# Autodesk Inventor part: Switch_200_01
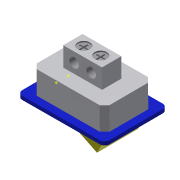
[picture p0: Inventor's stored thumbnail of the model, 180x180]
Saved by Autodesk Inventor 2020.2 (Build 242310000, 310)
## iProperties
Created: 2014-09
Part Number: Switch_200_01
Material: Ogólny
Document SubType Name: Modeling
Designer: F.Stasiak
Density: 1 g/cm^3
Appearance: Domyślna
Categories: <MemberInstance><Categories><Category DisplayName="" Mnemonic="CABLEANDHARNESS" InternalName="e4a7e005-5e42-4d16-b293-125e7f0d0512"><Category DisplayName="" Mne
Catalog Web Link: www.expertbooks.pl
Manager: www.cadconsulting.pl
Company: Fabian Stasiak CAD Consulting
GlobalPropertyList: <PropertyList/>
Author: F.Stasiak
Subject: Zbiór ćwiczeń. Autodesk Inventor 2020. Kurs Professional
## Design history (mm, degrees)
sketch "Szkic1"
  geometry: L1 (-10, 15)-(10, 15); L2 (10, 15)-(10, -15); L3 (10, -15)-(-10, -15); L4 (-10, -15)-(-10, 15); L5 (-10, 15)-(10, -15); L6 (10, 15)-(-10, -15); 1 further point
  constraints: 12 end point, 2 equal length, 2 midpoint, 1 horizontal, 1 parallel
  dimensions: "d0" = 20 distance of L2.end L3.end; "d1" = 30 distance of L1.end L2.end
extrude "Wyciągnięcie proste1" new body sketch "Szkic1" distance "d2" = 12; taper "d3" = 0 deg
node "Płaszczyzna konstrukcyjna1"
sketch "Szkic2"
  geometry: L1 (10, 15)-(-10, 15) reference; L2 (-10, 15)-(-10, -15) reference; L3 (-10, -15)-(10, -15) reference; L4 (10, -15)-(10, 15) reference; L5 (-13, 18)-(13, 18); L6 (13, 18)-(13, -18); L7 (13, -18)-(-13, -18); L8 (-13, -18)-(-13, 18); 1 further point
  constraints: 8 end point, 3 other
  dimensions: "d5" = 3 distance between parallel lines of L1 L5
extrude "Wyciągnięcie proste2" join sketch "Szkic2" distance "d6" = 1.5; taper "d7" = 0 deg
fillet "Zaokrąglenie1" dims "d8" = 2
chamfer "Faza1" distance "d9" = 2; stored, may be unused: second distance "d10" = 2, angle "d11" = 45 deg
sketch "Szkic3"
  geometry: L1 (15, 0)-(-15, 0) reference; L2 (-15, 0)-(15, 0) reference; L3 (13.059, 0)-(13.059, -1.168); L4 (13.059, -1.168)-(0.743, -1.599); L5 (0.743, -1.599)-(-10.298, -7.075); L6 (-10.298, -7.075)-(-13.229, -1.168); L7 (-13.229, -1.168)-(-13.229, 0); 1 further point
  constraints: 10 end point, 3 perpendicular, 2 equal length, 2 point on line
extrude "Wyciągnięcie proste3" join sketch "Szkic3" stored distance "d12" = 17; taper "d13" = 0 deg
sketch "Szkic4"
  geometry: L1 (4, 8)-(-4, 8); L2 (-4, 8)-(-4, -8); L3 (-4, -8)-(4, -8); L4 (4, -8)-(4, 8); L5 (4, 8)-(-4, -8); L6 (-4, 8)-(4, -8); 1 further point
  constraints: 12 end point, 2 midpoint, 2 parallel, 1 horizontal, 1 perpendicular
  dimensions: "d14" = 8 distance of L3.end L2.end; "d15" = 16 distance of L2.end L1.end
extrude "Wyciągnięcie proste4" join sketch "Szkic4" distance "d16" = 8; taper "d17" = 0 deg
sketch "Szkic5"
  geometry: L1 (0, 0)-(0, 16) reference; L2 (0, 0)-(8, 0) reference; L3 (8, 16)-(8, 0) reference; L4 (0, 16)-(8, 16) reference; L5 (4, 11.5)-(4, 4.5); C1 r 2 at (4, 11.5); C2 r 2 at (4, 4.5); 5 further points
  constraints: 4 midpoint, 2 centre point, 2 end point, 2 vertical alignment, 1 equal radius, 1 horizontal alignment, 1 vertical
  dimensions: "d18" = 4 diameter of C1; "d19" = 7 distance of L5.end L5.start
extrude "Wyciągnięcie proste5" cut sketch "Szkic5" distance "d20" = 5; taper "d21" = 0 deg
sketch "Szkic6"
  geometry: L1 (1, 1.5)-(1, 5.5) reference; L2 (-4, 1.5)-(-4, 5.5) reference; L3 (1, -5.5)-(1, -1.5) reference; L4 (-4, -5.5)-(-4, -1.5) reference; L5 (4, 8)-(-4, 8) reference; L6 (-4, 8)-(-4, -8) reference; L7 (-4, -8)-(4, -8) reference; L8 (4, -8)-(4, 8) reference; C1 r 2.5 at (0, 3.5); C2 r 2.5 at (0, -3.5); 2 further points
  constraints: 2 centre point, 2 midpoint, 2 vertical alignment, 1 equal radius
  dimensions: "d22" = 7 distance of C1.centre C2.centre; "d23" = 5 diameter of C2
extrude "Wyciągnięcie proste6" cut sketch "Szkic6" distance "d24" = 0.5; taper "d25" = 0 deg
sketch "Szkic7"
  geometry: L1 (0.3, 1.75)-(-0.3, 1.75); L2 (-0.3, 1.75)-(-0.3, -1.75); L3 (-0.3, -1.75)-(0.3, -1.75); L4 (0.3, -1.75)-(0.3, 1.75); L5 (0.3, 1.75)-(-0.3, -1.75); L6 (-0.3, 1.75)-(0.3, -1.75); L7 (1.8, 0.3)-(-1.8, 0.3); L8 (-1.8, 0.3)-(-1.8, -0.3); L9 (-1.8, -0.3)-(1.8, -0.3); L10 (1.8, -0.3)-(1.8, 0.3); L11 (1.8, 0.3)-(-1.8, -0.3); L12 (-1.8, 0.3)-(1.8, -0.3); 3 further points
  constraints: 24 end point, 5 midpoint, 4 parallel, 2 horizontal, 2 perpendicular
  dimensions: "d26" = 0.6 distance of L3.end L2.end; "d27" = 3.5 distance of L2.end L1.end; "d28" = 3.6 distance of L9.end L8.end; "d29" = 0.6 distance of L8.end L7.end
extrude "Wyciągnięcie proste7" cut sketch "Szkic7" distance "d30" = 1; taper "d31" = -5 deg
mirror "Odbicie lustrzane1"
chamfer "Faza2" distance "d32" = 1; stored, may be unused: second distance "d33" = 2, angle "d34" = 45 deg
chamfer "Faza3" distance "d35" = 1; stored, may be unused: second distance "d36" = 2, angle "d37" = 45 deg
node "Płaszczyzna konstrukcyjna5"
node "Płaszczyzna konstrukcyjna6"
node "Podejście - pkt 1"
node "Podejście - pkt 2"
node "Bryła1"
node "Pętla rzutowana1"
node "Pętla rzutowana2"
node "Pętla rzutowana3"
node "Pętla rzutowana4"
node "Pętla rzutowana5"
other parameters: "d4" = -1, "d40" = 5
